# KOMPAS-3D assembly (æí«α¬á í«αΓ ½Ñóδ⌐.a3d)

Referenced files in D:\МОДЕЛЬ ТАНКА Т90\ДЕТАЛИ\КОРПУС\МЕТАЛЛ\КОРПУС ЛИТОЙ\: корпус борт левый.m3d, ступица балансира.m3d, гидроамартизатор.m3d, посадка звездочки.m3d, посадка под линивец.m3d, грязеочеститель.m3d, упор балансира.m3d, кронштейн опорного катка.m3d, прилив.m3d, посадка под вал звездочки.m3d
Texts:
  Сборка борт левый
